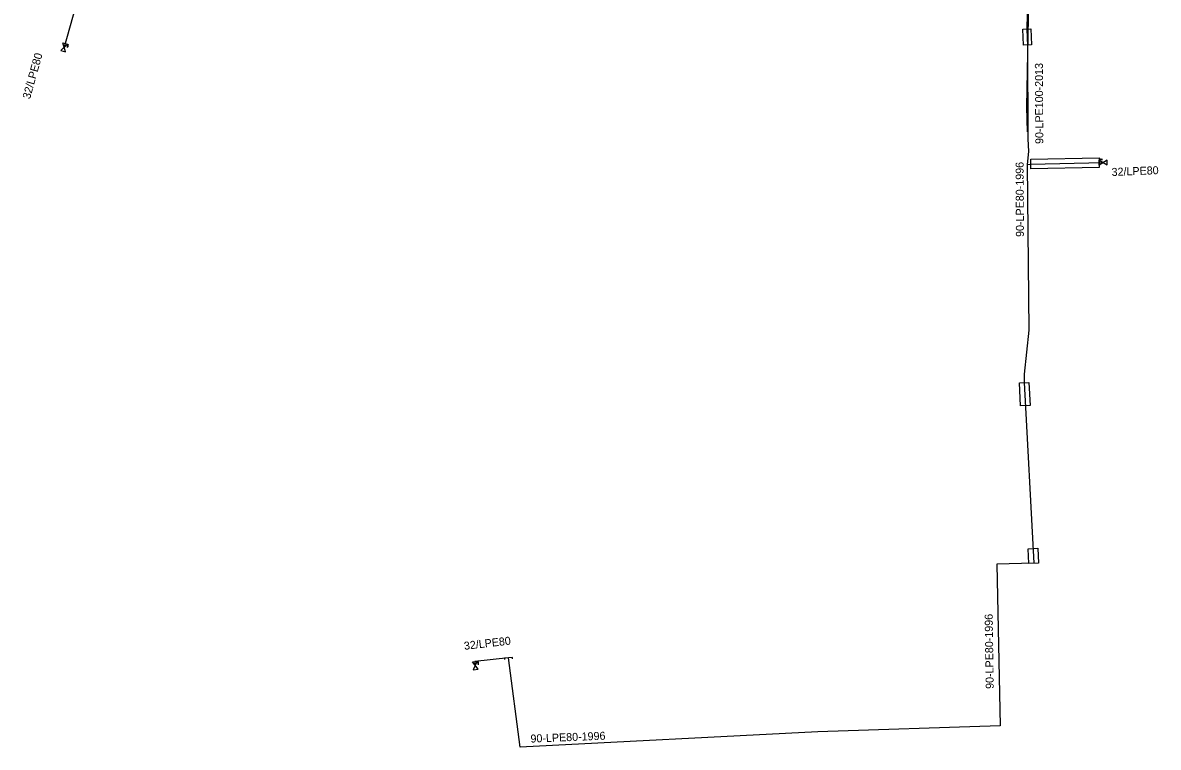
# Model space of a CAD drawing. Extents: x -741323 to -735641, y -1146295 to -1143223.
# Drawn here: x -736151.3 to -736009.4, y -1145565.1 to -1145474.6 of the extents above; entities that cross this region are included whole.
import ezdxf

# ---------------------------------------------------------------- set-up
doc = ezdxf.new("R2010")
doc.units = 0
for name, color, linetype in [('Vrstva 1', 7, 'Continuous'), ('Vrstva 21', 7, 'Continuous'), ('Vrstva 22', 7, 'Continuous'), ('Vrstva 29', 7, 'Continuous'), ('Vrstva 31', 7, 'Continuous'), ('Vrstva 32', 7, 'Continuous')]:
    doc.layers.add(name, color=color, linetype=linetype)

# ---------------------------------------------------------------- blocks, each defined once
blk = doc.blocks.new('DEC063-SN')
at = {"layer": 'Vrstva 1'}
for p, q in [((-0.5, -0.3), (0.5, 0.3)), ((0.5, -0.3), (-0.5, 0.3)), ((-0.5, 0.3), (-0.5, -0.3)), ((0.5, 0.3), (0.5, -0.3)), ((0.126, -0.318), (0.126, -0.458)), ((0.126, -0.384), (0.206, -0.384)), ((0.206, -0.458), (0.206, -0.318)), ((0.366, -0.458), (0.366, -0.318))]:
    blk.add_line(p, q, dxfattribs=at)
for points in [[(0.246, -0.318), (0.246, -0.418), (0.252, -0.438), (0.264, -0.451), (0.281, -0.458), (0.292, -0.458), (0.309, -0.451), (0.321, -0.438), (0.326, -0.418), (0.326, -0.318)], [(0.366, -0.318), (0.418, -0.318), (0.435, -0.325), (0.441, -0.331), (0.446, -0.344), (0.446, -0.364), (0.441, -0.378), (0.435, -0.384), (0.418, -0.391), (0.366, -0.391)]]:
    blk.add_lwpolyline(points, dxfattribs=at)
blk = doc.blocks.new('DEC130')
at = {"layer": 'Vrstva 1'}
blk.add_lwpolyline([(0.2, 0.5), (0, 0.5), (0, -0.5), (0.2, -0.5)], dxfattribs=at)

msp = doc.modelspace()

# ---------------------------------------------------------------- linework, layer by layer
at = {"layer": 'Vrstva 21'}
for points in [[(-736025.55, -1145468.06), (-736025.62, -1145471.75), (-736025.87, -1145485.1), (-736025.79, -1145488.23)], [(-736025.77, -1145471.8), (-736025.85, -1145475.37), (-736025.8, -1145476.51), (-736025.77, -1145477.39), (-736025.71, -1145489.09), (-736025.65, -1145490.66)], [(-736025.65, -1145490.66), (-736025.8, -1145492.28), (-736025.58, -1145513), (-736026.19, -1145518.47), (-736026.18, -1145519.54), (-736024.98, -1145542.1), (-736029.6, -1145542.23), (-736029.19, -1145562.38), (-736051.96, -1145563.14), (-736089.12, -1145565.08), (-736090.6, -1145553.89)]]:
    msp.add_lwpolyline(points, dxfattribs=at)
at = {"layer": 'Vrstva 29'}
for points in [[(-736025.35, -1145475.35), (-736025.27, -1145477.37), (-736026.27, -1145477.41), (-736026.35, -1145475.39)], [(-736025.34, -1145492.85), (-736025.36, -1145491.65), (-736016.83, -1145491.48), (-736016.81, -1145492.67)], [(-736026.78, -1145519.57), (-736025.58, -1145519.51), (-736025.43, -1145522.39), (-736026.62, -1145522.45)], [(-736025.68, -1145540.29), (-736024.48, -1145540.23), (-736024.38, -1145542.07), (-736025.58, -1145542.13)]]:
    msp.add_lwpolyline(points, close=True, dxfattribs=at)
at = {"layer": 'Vrstva 31'}
for points in [[(-736143.99, -1145470.18), (-736146.08, -1145477.65)], [(-736025.8, -1145492.28), (-736025.35, -1145492.25), (-736016.32, -1145492.06)], [(-736090.6, -1145553.89), (-736094.79, -1145554.38), (-736094.74, -1145554.87)]]:
    msp.add_lwpolyline(points, dxfattribs=at)

# ---------------------------------------------------------------- block references
at = {"layer": 'Vrstva 22', "rotation": -85.36198927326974}
msp.add_blockref('DEC130', (-736090.6, -1145553.89), dxfattribs=at)
at = {"layer": 'Vrstva 32'}
for p, rotation in [((-736146.08, -1145477.65), 74.38535000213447), ((-736016.32, -1145492.06), -179.04023881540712), ((-736094.74, -1145554.87), 95.74354167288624)]:
    msp.add_blockref('DEC063-SN', p, dxfattribs=dict(at, rotation=rotation))

# ---------------------------------------------------------------- texts
at = {"layer": 'Vrstva 21'}
for s, rotation, p in [('90-LPE100-2013', 90.294, (-736023.79, -1145489.73)), ('90-LPE80-1996', 90.245, (-736026.21, -1145501.34)), ('90-LPE80-1996', 90.842, (-736029.98, -1145557.78)), ('90-LPE80-1996', 2.286, (-736087.82, -1145564.5))]:
    msp.add_text(s, height=1, rotation=rotation, dxfattribs=at).set_placement(p)
at = {"layer": 'Vrstva 31'}
for rotation, p in [(74.385, (-736150.35, -1145484.19)), (2.349, (-736015.24, -1145493.74)), (6.67, (-736096.09, -1145552.92))]:
    msp.add_text('32/LPE80', height=1, rotation=rotation, dxfattribs=at).set_placement(p)

doc.saveas('drawing.dxf')
